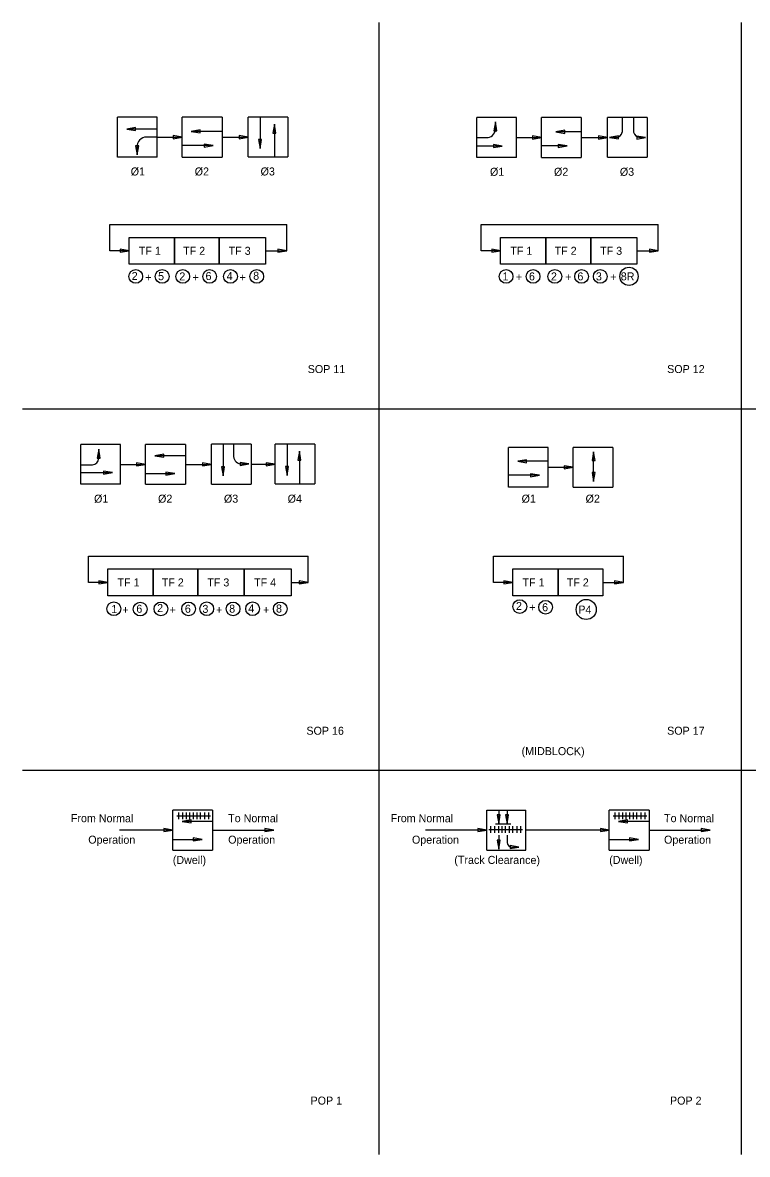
# Model space of a CAD drawing. Extents: x 10027 to 10797, y 10033 to 10528.
# Drawn here: x 10027.5 to 10344.3, y 10033.4 to 10528.4 of the extents above; entities that cross this region are included whole.
import ezdxf

# ---------------------------------------------------------------- set-up
doc = ezdxf.new("R2010")
doc.units = 0
for name, color, linetype in [('AdhocPoint_dp', 7, 'Continuous'), ('Default', 7, 'Continuous'), ('Dimension', 7, 'Continuous'), ('DSIndex', 7, 'Continuous'), ('SupstrConc', 7, 'Continuous')]:
    doc.layers.add(name, color=color, linetype=linetype)

msp = doc.modelspace()

# ---------------------------------------------------------------- linework, layer by layer
at = {"layer": 'AdhocPoint_dp'}
for p, q in [((10183.41, 10033.43), (10183.41, 10528.43)), ((10341.7, 10033.43), (10341.7, 10528.43)), ((10027.5, 10359.54), (10797.5, 10359.54)), ((10797.5, 10201.33), (10027.5, 10201.33))]:
    msp.add_line(p, q, dxfattribs=at)
at = {"layer": 'Default'}
for p, q in [((10086.37, 10487.03), (10068.98, 10487.03)), ((10068.98, 10469.64), (10068.98, 10487.03)), ((10086.37, 10469.64), (10086.37, 10487.03)), ((10097.26, 10469.64), (10097.26, 10487.03)), ((10114.66, 10487.03), (10097.26, 10487.03)), ((10114.66, 10487.03), (10114.66, 10469.64)), ((10126.07, 10469.71), (10126.07, 10487.11)), ((10143.46, 10487.11), (10126.07, 10487.11)), ((10131.33, 10487.11), (10131.33, 10473.38)), ((10143.46, 10487.11), (10143.46, 10469.71)), ((10243.44, 10486.89), (10226.04, 10486.89)), ((10226.04, 10469.5), (10226.04, 10486.89)), ((10243.44, 10469.5), (10243.44, 10486.89)), ((10254.33, 10469.5), (10254.33, 10486.89)), ((10271.72, 10486.89), (10254.33, 10486.89)), ((10271.72, 10486.89), (10271.72, 10469.5)), ((10283.13, 10469.57), (10283.13, 10486.97)), ((10300.53, 10486.97), (10283.13, 10486.97)), ((10289.59, 10486.97), (10289.59, 10480.49)), ((10294.59, 10486.97), (10294.59, 10480.49)), ((10300.53, 10486.97), (10300.53, 10469.57)), ((10086.33, 10481.88), (10073, 10481.88)), ((10114.56, 10480.82), (10101.22, 10480.82)), ((10137.56, 10484.05), (10137.56, 10469.71)), ((10234.2, 10481.71), (10234.2, 10482.13)), ((10271.72, 10480.68), (10260.62, 10480.68)), ((10086.37, 10478.34), (10081.66, 10478.34)), ((10086.37, 10478.34), (10097.26, 10478.34)), ((10110.75, 10474.65), (10097.16, 10474.65)), ((10114.66, 10478.34), (10126.07, 10478.34)), ((10226.04, 10478.19), (10230.18, 10478.19)), ((10237.18, 10474.43), (10226.04, 10474.43)), ((10243.44, 10478.19), (10254.33, 10478.19)), ((10265.49, 10474.51), (10254.33, 10474.51)), ((10271.72, 10478.19), (10283.13, 10478.19)), ((10086.37, 10469.64), (10068.98, 10469.64)), ((10077.57, 10473.96), (10077.57, 10470.65)), ((10097.26, 10469.64), (10114.66, 10469.64)), ((10126.07, 10469.71), (10143.46, 10469.71)), ((10243.44, 10469.5), (10226.04, 10469.5)), ((10254.33, 10469.5), (10271.72, 10469.5)), ((10283.13, 10469.57), (10300.53, 10469.57)), ((10065.58, 10440.15), (10142.98, 10440.15)), ((10065.58, 10428.63), (10065.58, 10440.15)), ((10142.98, 10428.63), (10142.98, 10440.15)), ((10227.98, 10440.15), (10305.39, 10440.15)), ((10227.98, 10428.63), (10227.98, 10440.15)), ((10305.39, 10428.63), (10305.39, 10440.15)), ((10074.08, 10428.63), (10065.58, 10428.63)), ((10133.62, 10428.63), (10142.98, 10428.63)), ((10236.48, 10428.63), (10227.98, 10428.63)), ((10296.02, 10428.63), (10305.39, 10428.63)), ((10070.34, 10343.92), (10052.95, 10343.92)), ((10052.95, 10326.53), (10052.95, 10343.92)), ((10070.34, 10326.53), (10070.34, 10343.92)), ((10098.63, 10343.92), (10081.24, 10343.92)), ((10081.24, 10326.53), (10081.24, 10343.92)), ((10098.63, 10343.92), (10098.63, 10326.53)), ((10110.04, 10326.6), (10110.04, 10344)), ((10127.44, 10344), (10110.04, 10344)), ((10115.14, 10344), (10115.14, 10330.27)), ((10119.71, 10344.04), (10119.71, 10339.33)), ((10127.44, 10344), (10127.44, 10326.6)), ((10137.84, 10326.66), (10137.84, 10344.05)), ((10155.24, 10344.05), (10137.84, 10344.05)), ((10143.12, 10344.05), (10143.12, 10330.33)), ((10148.49, 10340.99), (10148.49, 10326.66)), ((10155.24, 10344.05), (10155.24, 10326.66)), ((10257.26, 10342.66), (10239.87, 10342.66)), ((10239.87, 10325.27), (10239.87, 10342.66)), ((10257.26, 10325.27), (10257.26, 10342.66)), ((10268.15, 10325.27), (10268.15, 10342.66)), ((10285.55, 10342.66), (10268.15, 10342.66)), ((10277.13, 10327.78), (10277.13, 10340.75)), ((10285.55, 10342.66), (10285.55, 10325.27)), ((10098.61, 10339.02), (10085.27, 10339.02)), ((10257.26, 10336.59), (10243.93, 10336.59)), ((10052.95, 10334.98), (10058.04, 10334.98)), ((10052.95, 10331.62), (10066.78, 10331.62)), ((10070.34, 10335.23), (10081.24, 10335.23)), ((10081.24, 10331.19), (10094.05, 10331.19)), ((10098.63, 10335.23), (10110.04, 10335.23)), ((10127.44, 10335.3), (10137.84, 10335.3)), ((10257.26, 10333.97), (10268.15, 10333.97)), ((10070.34, 10326.53), (10052.95, 10326.53)), ((10081.24, 10326.53), (10098.63, 10326.53)), ((10110.04, 10326.6), (10127.44, 10326.6)), ((10137.84, 10326.66), (10155.24, 10326.66)), ((10253.45, 10330.43), (10239.87, 10330.43)), ((10257.26, 10325.27), (10239.87, 10325.27)), ((10268.15, 10325.27), (10285.55, 10325.27)), ((10056.25, 10295.11), (10152.32, 10295.11)), ((10056.25, 10283.59), (10056.25, 10295.11)), ((10152.32, 10283.59), (10152.32, 10295.11)), ((10233.31, 10295.11), (10290.17, 10295.11)), ((10233.31, 10283.59), (10233.31, 10295.11)), ((10290.17, 10283.59), (10290.17, 10295.11)), ((10064.74, 10283.59), (10056.25, 10283.59)), ((10144.88, 10283.59), (10152.32, 10283.59)), ((10241.8, 10283.59), (10233.31, 10283.59)), ((10281.15, 10283.59), (10290.17, 10283.59)), ((10110.57, 10183.94), (10093.18, 10183.94)), ((10093.18, 10166.55), (10093.18, 10183.94)), ((10095.74, 10180.11), (10095.74, 10183)), ((10097.5, 10180.11), (10097.5, 10183)), ((10099.18, 10180.11), (10099.18, 10183)), ((10100.63, 10180.11), (10100.63, 10183)), ((10102.19, 10180.11), (10102.19, 10183)), ((10103.84, 10180.11), (10103.84, 10183)), ((10105.29, 10180.11), (10105.29, 10183)), ((10107.16, 10180.11), (10107.16, 10183)), ((10108.83, 10180.11), (10108.83, 10183)), ((10110.57, 10183.94), (10110.57, 10166.55)), ((10230.43, 10166.55), (10230.43, 10183.94)), ((10230.43, 10183.94), (10247.55, 10183.94)), ((10235.63, 10183.94), (10235.63, 10177.96)), ((10239.27, 10183.94), (10239.27, 10177.96)), ((10247.55, 10166.55), (10247.55, 10183.94)), ((10301.36, 10183.94), (10283.96, 10183.94)), ((10283.96, 10166.55), (10283.96, 10183.94)), ((10286.53, 10180.11), (10286.53, 10183)), ((10288.29, 10180.11), (10288.29, 10183)), ((10289.96, 10180.11), (10289.96, 10183)), ((10291.41, 10180.11), (10291.41, 10183)), ((10292.97, 10180.11), (10292.97, 10183)), ((10294.62, 10180.11), (10294.62, 10183)), ((10296.07, 10180.11), (10296.07, 10183)), ((10297.95, 10180.11), (10297.95, 10183)), ((10299.62, 10180.11), (10299.62, 10183)), ((10301.36, 10183.94), (10301.36, 10166.55)), ((10094.9, 10181.53), (10109.6, 10181.53)), ((10110.55, 10179.04), (10097.21, 10179.04)), ((10234.25, 10177.96), (10240.95, 10177.96)), ((10285.69, 10181.53), (10300.39, 10181.53)), ((10301.34, 10179.04), (10288, 10179.04)), ((10093.18, 10175.24), (10069.86, 10175.24)), ((10110.57, 10175.24), (10137.26, 10175.24)), ((10230.43, 10175.24), (10203.69, 10175.24)), ((10231.37, 10175.5), (10246.08, 10175.5)), ((10232.21, 10174.08), (10232.21, 10176.97)), ((10233.97, 10174.08), (10233.97, 10176.97)), ((10235.63, 10173.05), (10235.63, 10166.93)), ((10235.65, 10174.08), (10235.65, 10176.97)), ((10237.1, 10174.08), (10237.1, 10176.97)), ((10238.66, 10174.08), (10238.66, 10176.97)), ((10239.27, 10173.05), (10239.27, 10169.81)), ((10240.31, 10174.08), (10240.31, 10176.97)), ((10241.76, 10174.08), (10241.76, 10176.97)), ((10243.63, 10174.08), (10243.63, 10176.97)), ((10245.31, 10174.08), (10245.31, 10176.97)), ((10283.96, 10175.24), (10247.55, 10175.24)), ((10301.36, 10175.24), (10328.05, 10175.24)), ((10093.18, 10171.21), (10105.99, 10171.21)), ((10241.23, 10167.85), (10244.49, 10167.85)), ((10283.96, 10171.21), (10296.78, 10171.21)), ((10093.18, 10166.55), (10110.57, 10166.55)), ((10230.43, 10166.55), (10247.55, 10166.55)), ((10283.96, 10166.55), (10301.36, 10166.55))]:
    msp.add_line(p, q, dxfattribs=at)
msp.add_circle((10292.59, 10417.44), 3.99, dxfattribs=at)
for centre, radius, start, end in [((10230.43, 10481.96), 3.78, 266.3242, 356.0955), ((10286.69, 10481.15), 2.97, 278.0762, 347.2625), ((10297.49, 10481.15), 2.97, 192.7375, 265.7067), ((10081.53, 10474.36), 3.98, 88.0112, 185.8153), ((10057.77, 10338), 3.03, 273.2123, 358.8254), ((10123.48, 10339.09), 3.78, 176.3242, 257.7005), ((10241.43, 10170.01), 2.17, 185.1228, 264.5013)]:
    msp.add_arc(centre, radius, start, end, dxfattribs=at)
at = {"layer": 'Dimension'}
for p, q in [((10234.2, 10482.13), (10234.18, 10484.99)), ((10287.11, 10478.2), (10284.06, 10478.2)), ((10297.26, 10478.18), (10299.84, 10478.18)), ((10060.79, 10337.94), (10060.79, 10341.84)), ((10122.67, 10335.4), (10126.44, 10335.4))]:
    msp.add_line(p, q, dxfattribs=at)
for centre, radius in [((10076.94, 10417.44), 3), ((10088.5, 10417.44), 3), ((10097.49, 10417.44), 3), ((10109.26, 10417.44), 3), ((10118.36, 10417.44), 3), ((10129.83, 10417.44), 3), ((10238.85, 10417.44), 3), ((10250.63, 10417.44), 3), ((10260.16, 10417.44), 3), ((10271.85, 10417.44), 3), ((10280.02, 10417.44), 3), ((10067.36, 10272.07), 3), ((10078.89, 10271.91), 3), ((10087.94, 10272.01), 3), ((10100.04, 10272), 3), ((10107.96, 10272.06), 3), ((10119.51, 10271.98), 3), ((10128.05, 10272.07), 3), ((10140.13, 10271.98), 3), ((10244.85, 10273.02), 3), ((10256.12, 10272.75), 3), ((10273.89, 10271.76), 4.39)]:
    msp.add_circle(centre, radius, dxfattribs=at)
at = {"layer": 'DSIndex'}
for points in [[(10074.08, 10434.51), (10093.82, 10434.51), (10093.82, 10422.75), (10074.08, 10422.75)], [(10093.82, 10434.51), (10113.43, 10434.51), (10113.43, 10422.75), (10093.82, 10422.75)], [(10113.43, 10434.51), (10133.62, 10434.51), (10133.62, 10422.75), (10113.43, 10422.75)], [(10236.48, 10434.51), (10256.22, 10434.51), (10256.22, 10422.75), (10236.48, 10422.75)], [(10256.22, 10434.51), (10275.83, 10434.51), (10275.83, 10422.75), (10256.22, 10422.75)], [(10275.83, 10434.51), (10296.02, 10434.51), (10296.02, 10422.75), (10275.83, 10422.75)], [(10064.74, 10289.47), (10084.49, 10289.47), (10084.49, 10277.71), (10064.74, 10277.71)], [(10084.49, 10289.47), (10104.1, 10289.47), (10104.1, 10277.71), (10084.49, 10277.71)], [(10104.1, 10289.47), (10124.29, 10289.47), (10124.29, 10277.71), (10104.1, 10277.71)], [(10124.29, 10289.47), (10144.88, 10289.47), (10144.88, 10277.71), (10124.29, 10277.71)], [(10241.8, 10289.47), (10261.55, 10289.47), (10261.55, 10277.71), (10241.8, 10277.71)], [(10261.55, 10289.47), (10281.15, 10289.47), (10281.15, 10277.71), (10261.55, 10277.71)]]:
    msp.add_lwpolyline(points, close=True, dxfattribs=at)
at = {"layer": 'SupstrConc'}
for points in [[(10234.18, 10484.99), (10233.54, 10481.08), (10234.86, 10481.08)], [(10073, 10481.88), (10076.9, 10481.21), (10076.9, 10482.54)], [(10101.22, 10480.82), (10105.13, 10480.16), (10105.13, 10481.48)], [(10137.56, 10484.05), (10136.9, 10480.14), (10138.22, 10480.14)], [(10260.62, 10480.68), (10264.52, 10480.01), (10264.52, 10481.34)], [(10077.57, 10470.65), (10078.23, 10474.56), (10076.91, 10474.56)], [(10097.26, 10478.34), (10093.36, 10479), (10093.36, 10477.67)], [(10110.75, 10474.65), (10106.84, 10475.31), (10106.84, 10473.99)], [(10126.07, 10478.34), (10122.16, 10479), (10122.16, 10477.67)], [(10131.33, 10473.38), (10131.99, 10477.29), (10130.66, 10477.29)], [(10237.18, 10474.43), (10233.28, 10475.09), (10233.28, 10473.77)], [(10254.33, 10478.19), (10250.42, 10478.86), (10250.42, 10477.53)], [(10265.49, 10474.51), (10261.58, 10475.17), (10261.58, 10473.85)], [(10283.13, 10478.19), (10279.23, 10478.86), (10279.23, 10477.53)], [(10284.06, 10478.2), (10287.96, 10477.54), (10287.96, 10478.86)], [(10299.84, 10478.18), (10295.94, 10478.84), (10295.94, 10477.52)], [(10074.08, 10428.63), (10070.17, 10429.29), (10070.17, 10427.97)], [(10142.98, 10428.63), (10139.08, 10429.29), (10139.08, 10427.97)], [(10236.48, 10428.63), (10232.58, 10429.29), (10232.58, 10427.97)], [(10305.39, 10428.63), (10301.48, 10429.29), (10301.48, 10427.97)], [(10060.79, 10341.84), (10060.13, 10337.94), (10061.45, 10337.94)], [(10148.49, 10340.99), (10147.83, 10337.09), (10149.15, 10337.09)], [(10277.13, 10340.75), (10276.47, 10336.85), (10277.8, 10336.85)], [(10081.24, 10335.23), (10077.33, 10335.89), (10077.33, 10334.56)], [(10085.27, 10339.02), (10089.18, 10338.36), (10089.18, 10339.68)], [(10110.04, 10335.23), (10106.14, 10335.89), (10106.14, 10334.56)], [(10126.44, 10335.4), (10122.53, 10336.06), (10122.53, 10334.73)], [(10137.84, 10335.3), (10133.93, 10335.96), (10133.93, 10334.64)], [(10243.93, 10336.59), (10247.83, 10335.93), (10247.83, 10337.26)], [(10066.78, 10331.62), (10062.87, 10332.28), (10062.87, 10330.95)], [(10094.05, 10331.19), (10090.15, 10331.86), (10090.15, 10330.53)], [(10115.14, 10330.27), (10115.8, 10334.18), (10114.48, 10334.18)], [(10143.12, 10330.33), (10143.78, 10334.23), (10142.46, 10334.23)], [(10253.45, 10330.43), (10249.55, 10331.09), (10249.55, 10329.77)], [(10268.15, 10333.97), (10264.25, 10334.63), (10264.25, 10333.31)], [(10277.13, 10327.78), (10277.8, 10331.68), (10276.47, 10331.68)], [(10064.74, 10283.59), (10060.84, 10284.25), (10060.84, 10282.93)], [(10152.32, 10283.59), (10148.41, 10284.25), (10148.41, 10282.93)], [(10241.8, 10283.59), (10237.9, 10284.25), (10237.9, 10282.93)], [(10290.17, 10283.59), (10286.27, 10284.25), (10286.27, 10282.93)], [(10097.21, 10179.04), (10101.12, 10178.38), (10101.12, 10179.7)], [(10235.63, 10177.96), (10236.29, 10181.87), (10234.97, 10181.87)], [(10239.27, 10177.96), (10239.94, 10181.87), (10238.61, 10181.87)], [(10288, 10179.04), (10291.91, 10178.38), (10291.91, 10179.7)], [(10093.18, 10175.24), (10089.27, 10175.91), (10089.27, 10174.58)], [(10137.26, 10175.24), (10133.36, 10175.91), (10133.36, 10174.58)], [(10230.43, 10175.24), (10226.52, 10175.91), (10226.52, 10174.58)], [(10283.96, 10175.24), (10280.06, 10175.91), (10280.06, 10174.58)], [(10328.05, 10175.24), (10324.15, 10175.91), (10324.15, 10174.58)], [(10105.99, 10171.21), (10102.09, 10171.88), (10102.09, 10170.55)], [(10105.99, 10171.21), (10102.09, 10171.88), (10102.09, 10170.55)], [(10235.63, 10166.93), (10236.29, 10170.84), (10234.97, 10170.84)], [(10244.49, 10167.85), (10240.59, 10168.51), (10240.59, 10167.18)], [(10296.78, 10171.21), (10292.87, 10171.88), (10292.87, 10170.55)]]:
    msp.add_lwpolyline(points, close=True, dxfattribs=at)

# ---------------------------------------------------------------- texts
at = {"layer": 'Dimension'}
for s, p in [('Ø1', (10074.75, 10461.58)), ('Ø2', (10102.72, 10461.58)), ('Ø3', (10131.52, 10461.58)), ('Ø1', (10231.81, 10461.44)), ('Ø2', (10259.79, 10461.44)), ('Ø3', (10288.59, 10461.44)), ('TF 1', (10078.3, 10426.88)), ('TF 2', (10097.66, 10426.88)), ('TF 3', (10117.55, 10426.88)), ('TF 1', (10240.7, 10426.88)), ('TF 2', (10260.06, 10426.88)), ('TF 3', (10279.96, 10426.88)), ('+', (10081.04, 10415.27)), ('+', (10101.75, 10415.27)), ('+', (10122.36, 10415.27)), ('+', (10243.14, 10415.45)), ('+', (10264.66, 10415.45)), ('+', (10284.33, 10415.45)), ('8R', (10288.99, 10415.69)), ('Ø1', (10058.72, 10318.47)), ('Ø2', (10086.7, 10318.47)), ('Ø3', (10115.5, 10318.47)), ('Ø4', (10143.37, 10318.47)), ('Ø1', (10245.64, 10318.47)), ('Ø2', (10273.61, 10318.47)), ('TF 1', (10068.96, 10281.84)), ('TF 2', (10088.33, 10281.84)), ('TF 3', (10108.22, 10281.84)), ('TF 4', (10128.68, 10281.84)), ('TF 1', (10246.02, 10281.84)), ('TF 2', (10265.38, 10281.84)), ('+', (10071.11, 10269.87)), ('+', (10091.76, 10269.87)), ('+', (10112.07, 10269.87)), ('+', (10132.58, 10269.87)), ('+', (10248.99, 10270.9)), ('P4', (10270.43, 10269.98))]:
    msp.add_text(s, height=3.5, dxfattribs=at).set_placement(p)
for s, rotation, p in [('2', 359.6943, (10075.18, 10415.86)), ('5', 359.6943, (10086.71, 10415.8)), ('2', 359.6943, (10095.98, 10415.7)), ('6', 359.6943, (10107.45, 10415.85)), ('4', 359.6943, (10116.67, 10415.85)), ('8', 359.6943, (10128.27, 10415.95)), ('1', 359.6943, (10237.27, 10415.69)), ('6', 359.6943, (10248.84, 10415.7)), ('2', 359.6943, (10258.45, 10415.7)), ('6', 359.6943, (10270.03, 10415.7)), ('3', 359.6943, (10278.1, 10415.7)), ('SOP 11', 359.8217, (10152.13, 10375.18)), ('SOP 12', 359.8217, (10309.26, 10375.18)), ('1', 359.6943, (10066.2, 10270.17)), ('6', 359.6943, (10077.2, 10270.32)), ('2', 359.6943, (10086.29, 10270.64)), ('6', 359.6943, (10098.4, 10270.33)), ('3', 359.6943, (10106.09, 10270.27)), ('8', 359.6943, (10117.79, 10270.36)), ('4', 359.6943, (10126.12, 10270.47)), ('8', 359.6943, (10138.26, 10270.42)), ('2', 359.6943, (10243.16, 10271.55)), ('6', 359.6943, (10254.6, 10270.99)), ('SOP 16', 359.8217, (10151.55, 10216.99)), ('SOP 17', 359.8217, (10309.25, 10216.99)), ('(MIDBLOCK)', 359.8217, (10245.62, 10208.1)), ('From Normal', 359.8217, (10048.59, 10178.74)), ('To Normal', 359.8217, (10117.35, 10178.73)), ('From Normal', 359.8217, (10188.39, 10178.74)), ('To Normal', 359.8217, (10307.91, 10178.73)), ('Operation', 359.8217, (10056.18, 10169.33)), ('Operation', 359.8217, (10117.35, 10169.33)), ('Operation', 359.8217, (10197.7, 10169.33)), ('Operation', 359.8217, (10307.91, 10169.33)), ('(Dwell)', 359.8217, (10093.14, 10160.47)), ('(Track Clearance)', 359.8217, (10216.22, 10160.52)), ('(Dwell)', 359.8217, (10283.93, 10160.47)), ('POP 1', 359.8217, (10153.36, 10055.21)), ('POP 2', 359.8217, (10310.49, 10055.21))]:
    msp.add_text(s, height=3.5, rotation=rotation, dxfattribs=at).set_placement(p)

doc.saveas('drawing.dxf')
